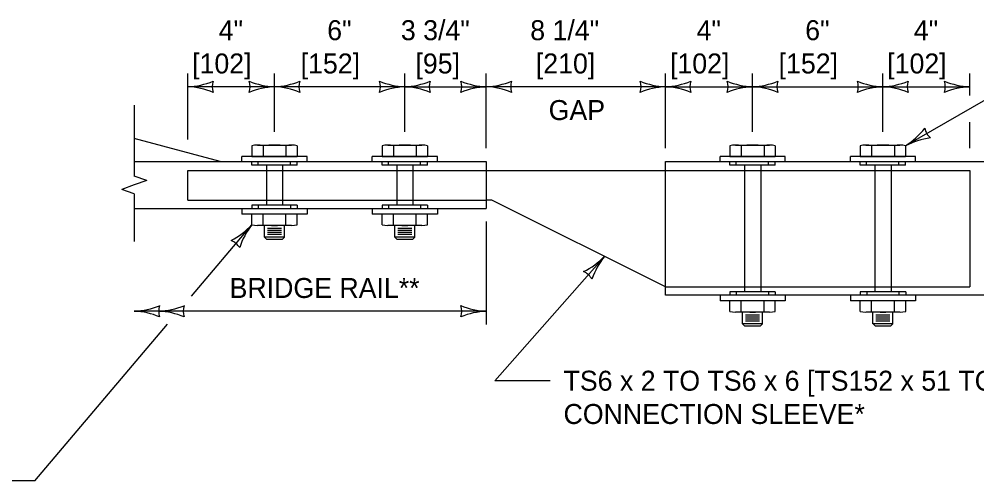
# Model space of a CAD drawing. Extents: x 49991.4 to 50021, y 49987.6 to 50011.4.
# Drawn here: x 50011.465 to 50014.342, y 49993.536 to 49994.923 of the extents above; entities that cross this region are included whole.
import ezdxf

# ---------------------------------------------------------------- set-up
doc = ezdxf.new("R2010")
doc.units = 0
for name, color, linetype in [('Level 1', 7, 'Continuous'), ('Level 2', 7, 'Continuous'), ('Level 3', 7, 'Continuous'), ('Level 4', 7, 'Continuous'), ('Level 6', 7, 'Continuous')]:
    doc.layers.add(name, color=color, linetype=linetype)

msp = doc.modelspace()

# ---------------------------------------------------------------- linework, layer by layer
at = {"layer": 'Level 1'}
for p, q in [((50012.0685, 49994.495), (50011.8107, 49994.5642)), ((50012.1636, 49994.5423), (50012.1636, 49994.5105)), ((50012.1807, 49994.5444), (50012.2828, 49994.5444)), ((50012.1974, 49994.5423), (50012.1974, 49994.5106)), ((50012.2662, 49994.5423), (50012.2662, 49994.5106)), ((50012.3, 49994.5423), (50012.3, 49994.5105)), ((50012.5551, 49994.5424), (50012.5551, 49994.5106)), ((50012.5722, 49994.5445), (50012.6743, 49994.5445)), ((50012.5889, 49994.5425), (50012.5889, 49994.5107)), ((50012.6577, 49994.5425), (50012.6577, 49994.5107)), ((50012.6915, 49994.5424), (50012.6915, 49994.5106)), ((50013.5997, 49994.5424), (50013.5997, 49994.5106)), ((50013.6168, 49994.5445), (50013.7189, 49994.5445)), ((50013.6335, 49994.5424), (50013.6335, 49994.5107)), ((50013.7023, 49994.5424), (50013.7023, 49994.5107)), ((50013.7361, 49994.5424), (50013.7361, 49994.5106)), ((50013.9913, 49994.5424), (50013.9913, 49994.5106)), ((50014.0084, 49994.5445), (50014.1105, 49994.5445)), ((50014.0251, 49994.5424), (50014.0251, 49994.5107)), ((50014.0939, 49994.5424), (50014.0939, 49994.5107)), ((50014.1277, 49994.5424), (50014.1277, 49994.5106)), ((50012.3295, 49994.5105), (50012.1341, 49994.5105)), ((50012.1341, 49994.495), (50012.1341, 49994.5105)), ((50012.1636, 49994.5105), (50012.3, 49994.5105)), ((50012.3295, 49994.495), (50012.3295, 49994.5105)), ((50012.721, 49994.5106), (50012.5256, 49994.5106)), ((50012.5256, 49994.4951), (50012.5256, 49994.5106)), ((50012.5551, 49994.5106), (50012.6915, 49994.5106)), ((50012.721, 49994.4951), (50012.721, 49994.5106)), ((50013.7656, 49994.5106), (50013.5702, 49994.5106)), ((50013.5702, 49994.4951), (50013.5702, 49994.5106)), ((50013.5997, 49994.5106), (50013.7361, 49994.5106)), ((50013.7656, 49994.4951), (50013.7656, 49994.5106)), ((50014.1572, 49994.5106), (50013.9618, 49994.5106)), ((50013.9618, 49994.4951), (50013.9618, 49994.5106)), ((50013.9913, 49994.5106), (50014.1277, 49994.5106)), ((50014.1572, 49994.4951), (50014.1572, 49994.5106)), ((50011.8107, 49994.495), (50012.8678, 49994.495)), ((50012.8683, 49994.3544), (50012.8683, 49994.4951)), ((50013.4063, 49994.495), (50014.4453, 49994.495)), ((50013.4068, 49994.094), (50013.4068, 49994.4951)), ((50012.8683, 49994.4681), (50013.4068, 49994.4681)), ((50012.868, 49994.3795), (50012.8847, 49994.3795)), ((50013.4068, 49994.1186), (50012.8845, 49994.379)), ((50011.8107, 49994.3544), (50012.8678, 49994.3544)), ((50012.1341, 49994.3544), (50012.1341, 49994.337)), ((50012.3295, 49994.337), (50012.1341, 49994.337)), ((50012.3, 49994.337), (50012.1636, 49994.337)), ((50012.1636, 49994.3052), (50012.1636, 49994.337)), ((50012.1974, 49994.3051), (50012.1974, 49994.3369)), ((50012.2662, 49994.3051), (50012.2662, 49994.3369)), ((50012.3, 49994.3052), (50012.3, 49994.337)), ((50012.3295, 49994.3544), (50012.3295, 49994.337)), ((50012.5256, 49994.3544), (50012.5256, 49994.337)), ((50012.721, 49994.337), (50012.5256, 49994.337)), ((50012.6915, 49994.337), (50012.5551, 49994.337)), ((50012.5551, 49994.3052), (50012.5551, 49994.337)), ((50012.5889, 49994.3051), (50012.5889, 49994.3369)), ((50012.6577, 49994.3051), (50012.6577, 49994.3369)), ((50012.6915, 49994.3052), (50012.6915, 49994.337)), ((50012.721, 49994.3544), (50012.721, 49994.337)), ((50012.2829, 49994.3031), (50012.1808, 49994.3031)), ((50012.2018, 49994.2675), (50012.2018, 49994.303)), ((50012.2618, 49994.2675), (50012.2618, 49994.303)), ((50012.6744, 49994.3031), (50012.5723, 49994.3031)), ((50012.5933, 49994.2675), (50012.5933, 49994.303)), ((50012.6533, 49994.2675), (50012.6533, 49994.303)), ((50012.2106, 49994.2947), (50012.2527, 49994.2947)), ((50012.2106, 49994.2887), (50012.2527, 49994.2887)), ((50012.2106, 49994.2827), (50012.2527, 49994.2827)), ((50012.2106, 49994.2767), (50012.2527, 49994.2767)), ((50012.6021, 49994.2947), (50012.6442, 49994.2947)), ((50012.6021, 49994.2887), (50012.6442, 49994.2887)), ((50012.6021, 49994.2827), (50012.6442, 49994.2827)), ((50012.6021, 49994.2767), (50012.6442, 49994.2767)), ((50012.2618, 49994.2675), (50012.2018, 49994.2675)), ((50012.2019, 49994.2676), (50012.2079, 49994.2616)), ((50012.2079, 49994.2616), (50012.2558, 49994.2616)), ((50012.2617, 49994.2676), (50012.2558, 49994.2616)), ((50012.6533, 49994.2675), (50012.5933, 49994.2675)), ((50012.5934, 49994.2676), (50012.5994, 49994.2616)), ((50012.5994, 49994.2616), (50012.6473, 49994.2616)), ((50012.6532, 49994.2676), (50012.6473, 49994.2616)), ((50013.4063, 49994.0942), (50014.4453, 49994.0942)), ((50013.5702, 49994.094), (50013.5702, 49994.0766)), ((50013.7656, 49994.0766), (50013.5702, 49994.0766)), ((50013.7361, 49994.0766), (50013.5997, 49994.0766)), ((50013.5997, 49994.0448), (50013.5997, 49994.0766)), ((50013.6335, 49994.0447), (50013.6335, 49994.0765)), ((50013.7023, 49994.0447), (50013.7023, 49994.0765)), ((50013.7361, 49994.0448), (50013.7361, 49994.0766)), ((50013.7656, 49994.094), (50013.7656, 49994.0766)), ((50013.962, 49994.094), (50013.962, 49994.0766)), ((50014.1574, 49994.0766), (50013.962, 49994.0766)), ((50014.1279, 49994.0766), (50013.9915, 49994.0766)), ((50013.9915, 49994.0448), (50013.9915, 49994.0766)), ((50014.0253, 49994.0447), (50014.0253, 49994.0765)), ((50014.0941, 49994.0447), (50014.0941, 49994.0765)), ((50014.1279, 49994.0448), (50014.1279, 49994.0766)), ((50014.1574, 49994.094), (50014.1574, 49994.0766)), ((50013.719, 49994.0427), (50013.6169, 49994.0427)), ((50013.6379, 49994.0071), (50013.6379, 49994.0426)), ((50013.6467, 49994.0343), (50013.6888, 49994.0343)), ((50013.6467, 49994.0283), (50013.6888, 49994.0283)), ((50013.6467, 49994.0223), (50013.6888, 49994.0223)), ((50013.6467, 49994.0163), (50013.6888, 49994.0163)), ((50013.6979, 49994.0071), (50013.6979, 49994.0426)), ((50014.1108, 49994.0427), (50014.0087, 49994.0427)), ((50014.0297, 49994.0071), (50014.0297, 49994.0426)), ((50014.0385, 49994.0343), (50014.0806, 49994.0343)), ((50014.0385, 49994.0283), (50014.0806, 49994.0283)), ((50014.0385, 49994.0223), (50014.0806, 49994.0223)), ((50014.0385, 49994.0163), (50014.0806, 49994.0163)), ((50014.0897, 49994.0071), (50014.0897, 49994.0426)), ((50013.6979, 49994.0071), (50013.6379, 49994.0071)), ((50013.638, 49994.0072), (50013.644, 49994.0012)), ((50013.644, 49994.0012), (50013.6919, 49994.0012)), ((50013.6978, 49994.0072), (50013.6919, 49994.0012)), ((50014.0897, 49994.0071), (50014.0297, 49994.0071)), ((50014.0298, 49994.0072), (50014.0358, 49994.0012)), ((50014.0358, 49994.0012), (50014.0837, 49994.0012)), ((50014.0896, 49994.0072), (50014.0837, 49994.0012))]:
    msp.add_line(p, q, dxfattribs=at)
for centre, major_axis, start_param, end_param in [((50012.1806, 49994.5283), (0.0341, 0), 1.056847, 2.094396), ((50012.2318, 49994.4801), (0.1365, 0), 1.315951, 1.825641), ((50012.283, 49994.5283), (0.0341, 0), 1.047198, 2.084746), ((50012.5721, 49994.5284), (0.0341, 0), 1.056847, 2.094396), ((50012.6233, 49994.4802), (0.1365, 0), 1.315951, 1.825641), ((50012.6745, 49994.5284), (0.0341, 0), 1.047198, 2.084746), ((50013.6167, 49994.5284), (0.0341, 0), 1.056847, 2.094396), ((50013.6679, 49994.4802), (0.1365, 0), 1.315951, 1.825641), ((50013.7191, 49994.5284), (0.0341, 0), 1.047198, 2.084746), ((50014.0083, 49994.5284), (0.0341, 0), 1.056847, 2.094396), ((50014.0595, 49994.4802), (0.1365, 0), 1.315951, 1.825641), ((50014.1107, 49994.5284), (0.0341, 0), 1.047198, 2.084746), ((50012.1806, 49994.3192), (-0.0341, 0), 1.047198, 2.084746), ((50012.2318, 49994.3674), (-0.1365, 0), 1.315951, 1.825641), ((50012.283, 49994.3192), (-0.0341, 0), 1.056847, 2.094396), ((50012.5721, 49994.3192), (-0.0341, 0), 1.047198, 2.084746), ((50012.6233, 49994.3674), (-0.1365, 0), 1.315951, 1.825641), ((50012.6745, 49994.3192), (-0.0341, 0), 1.056847, 2.094396), ((50013.6167, 49994.0588), (-0.0341, 0), 1.047198, 2.084746), ((50013.6679, 49994.107), (-0.1365, 0), 1.315951, 1.825641), ((50013.7191, 49994.0588), (-0.0341, 0), 1.056847, 2.094396), ((50014.0085, 49994.0588), (-0.0341, 0), 1.047198, 2.084746), ((50014.0597, 49994.107), (-0.1365, 0), 1.315951, 1.825641), ((50014.1109, 49994.0588), (-0.0341, 0), 1.056847, 2.094396)]:
    msp.add_ellipse(centre, major_axis=major_axis, ratio=0.471622, start_param=start_param, end_param=end_param, dxfattribs=at)
at = {"layer": 'Level 3'}
for p, q in [((50014.7294, 49994.8897), (50014.1277, 49994.5424)), ((50011.9713, 49994.5611), (50011.9713, 49994.7597)), ((50012.2317, 49994.5844), (50012.2317, 49994.7597)), ((50012.6232, 49994.5845), (50012.6232, 49994.7597)), ((50012.8678, 49994.535), (50012.8678, 49994.7597)), ((50013.4063, 49994.535), (50013.4063, 49994.7597)), ((50013.6678, 49994.5845), (50013.6678, 49994.7597)), ((50014.059, 49994.5845), (50014.059, 49994.7597)), ((50014.3204, 49994.6936), (50014.3204, 49994.7597)), ((50012.2317, 49994.7197), (50011.9713, 49994.7197)), ((50012.6232, 49994.7197), (50012.2317, 49994.7197)), ((50012.6232, 49994.7197), (50012.8678, 49994.7197)), ((50013.4063, 49994.7197), (50012.8678, 49994.7197)), ((50013.4063, 49994.7197), (50013.6678, 49994.7197)), ((50013.6678, 49994.7197), (50014.059, 49994.7197)), ((50014.059, 49994.7197), (50014.3204, 49994.7197)), ((50014.3204, 49994.535), (50014.3204, 49994.6136)), ((50011.9822, 49994.0909), (50012.1636, 49994.3052)), ((50012.8678, 49994.3144), (50012.8678, 49994.0052)), ((50012.8937, 49993.8365), (50013.2232, 49994.2102)), ((50012.8678, 49994.0452), (50011.8107, 49994.0452)), ((50011.5123, 49993.5356), (50011.9105, 49994.0062)), ((50013.0601, 49993.8365), (50012.8937, 49993.8365)), ((50011.5123, 49993.5356), (50010.9895, 49993.5356))]:
    msp.add_line(p, q, dxfattribs=at)
for centre, radius, start, end in [((50011.9598, 49994.9524), 0.233, 272.8273, 292.0772), ((50012.0995, 49994.7197), 0.0548, 162.1388, 197.8612), ((50012.2409, 49994.9418), 0.2223, 247.456, 267.6395), ((50012.1035, 49994.7197), 0.0548, 342.1388, 17.8612), ((50012.2203, 49994.9524), 0.233, 272.8273, 292.0772), ((50012.36, 49994.7197), 0.0548, 162.1388, 197.8612), ((50012.6324, 49994.9418), 0.2223, 247.456, 267.6395), ((50012.495, 49994.7197), 0.0548, 342.1388, 17.8612), ((50012.6118, 49994.9524), 0.233, 272.8273, 292.0772), ((50012.7515, 49994.7197), 0.0548, 162.1388, 197.8612), ((50012.877, 49994.9418), 0.2223, 247.456, 267.6395), ((50012.7396, 49994.7197), 0.0548, 342.1388, 17.8612), ((50012.8563, 49994.9524), 0.233, 272.8273, 292.0772), ((50012.9961, 49994.7197), 0.0548, 162.1388, 197.8612), ((50013.4155, 49994.9418), 0.2223, 247.456, 267.6395), ((50013.2781, 49994.7197), 0.0548, 342.1388, 17.8612), ((50013.3948, 49994.9524), 0.233, 272.8273, 292.0772), ((50013.5346, 49994.7197), 0.0548, 162.1388, 197.8612), ((50013.6769, 49994.9418), 0.2223, 247.456, 267.6395), ((50013.5395, 49994.7197), 0.0548, 342.1388, 17.8612), ((50013.6563, 49994.9524), 0.233, 272.8273, 292.0772), ((50013.796, 49994.7197), 0.0548, 162.1388, 197.8612), ((50014.0681, 49994.9418), 0.2223, 247.456, 267.6395), ((50013.9307, 49994.7197), 0.0548, 342.1388, 17.8612), ((50014.0475, 49994.9524), 0.233, 272.8273, 292.0772), ((50014.1872, 49994.7197), 0.0548, 162.1388, 197.8612), ((50014.3295, 49994.9418), 0.2223, 247.456, 267.6395), ((50014.1921, 49994.7197), 0.0548, 342.1388, 17.8612), ((50011.9621, 49994.4976), 0.2223, 67.456, 87.6395), ((50012.2432, 49994.487), 0.233, 92.8273, 112.0772), ((50012.2226, 49994.4976), 0.2223, 67.456, 87.6395), ((50012.6347, 49994.487), 0.233, 92.8273, 112.0772), ((50012.6141, 49994.4976), 0.2223, 67.456, 87.6395), ((50012.8793, 49994.487), 0.233, 92.8273, 112.0772), ((50012.8587, 49994.4976), 0.2223, 67.456, 87.6395), ((50013.4178, 49994.487), 0.233, 92.8273, 112.0772), ((50013.3972, 49994.4976), 0.2223, 67.456, 87.6395), ((50013.6792, 49994.487), 0.233, 92.8273, 112.0772), ((50013.6586, 49994.4976), 0.2223, 67.456, 87.6395), ((50014.0704, 49994.487), 0.233, 92.8273, 112.0772), ((50014.0498, 49994.4976), 0.2223, 67.456, 87.6395), ((50014.3319, 49994.487), 0.233, 92.8273, 112.0772), ((50014.0014, 49994.7382), 0.233, 302.8248, 322.0747), ((50014.2388, 49994.6065), 0.0548, 192.1363, 227.8587), ((50014.2309, 49994.3454), 0.2223, 97.4535, 117.637), ((50011.9999, 49994.4557), 0.2223, 297.2185, 317.402), ((50012.3486, 49994.1637), 0.233, 142.5898, 161.8396), ((50012.0807, 49994.2073), 0.0548, 31.9013, 67.6237), ((50013.0626, 49994.364), 0.2223, 296.0525, 316.236), ((50013.4054, 49994.0649), 0.233, 141.4238, 160.6737), ((50013.1384, 49994.114), 0.0548, 30.7353, 66.4577), ((50011.7992, 49994.2779), 0.233, 272.8273, 292.0772), ((50011.8015, 49993.823), 0.2223, 67.456, 87.6395), ((50011.8726, 49994.2779), 0.233, 272.8273, 292.0772), ((50011.9389, 49994.0452), 0.0548, 162.1388, 197.8612), ((50011.875, 49993.823), 0.2223, 67.456, 87.6395), ((50012.0124, 49994.0452), 0.0548, 162.1388, 197.8612), ((50012.877, 49994.2673), 0.2223, 247.456, 267.6395), ((50012.7396, 49994.0452), 0.0548, 342.1388, 17.8612), ((50012.8793, 49993.8125), 0.233, 92.8273, 112.0772)]:
    msp.add_arc(centre, radius, start, end, dxfattribs=at)
at = {"layer": 'Level 4'}
for p, q in [((50012.1635, 49994.484), (50012.1635, 49994.495)), ((50012.3, 49994.484), (50012.1635, 49994.484)), ((50012.1828, 49994.484), (50012.1828, 49994.495)), ((50012.2076, 49994.484), (50012.2076, 49994.3644)), ((50012.2563, 49994.484), (50012.2563, 49994.3644)), ((50012.2794, 49994.484), (50012.2794, 49994.495)), ((50012.3, 49994.484), (50012.3, 49994.495)), ((50012.555, 49994.4841), (50012.555, 49994.4951)), ((50012.6915, 49994.4841), (50012.555, 49994.4841)), ((50012.5743, 49994.4841), (50012.5743, 49994.4951)), ((50012.5991, 49994.4841), (50012.5991, 49994.3644)), ((50012.6478, 49994.4841), (50012.6478, 49994.3644)), ((50012.6709, 49994.4841), (50012.6709, 49994.4951)), ((50012.6915, 49994.4841), (50012.6915, 49994.4951)), ((50013.5996, 49994.4841), (50013.5996, 49994.4951)), ((50013.7361, 49994.4841), (50013.5996, 49994.4841)), ((50013.6189, 49994.4841), (50013.6189, 49994.4951)), ((50013.6437, 49994.4841), (50013.6437, 49994.104)), ((50013.6924, 49994.4841), (50013.6924, 49994.104)), ((50013.7155, 49994.4841), (50013.7155, 49994.4951)), ((50013.7361, 49994.4841), (50013.7361, 49994.4951)), ((50013.9912, 49994.4841), (50013.9912, 49994.4951)), ((50014.1277, 49994.4841), (50013.9912, 49994.4841)), ((50014.0105, 49994.4841), (50014.0105, 49994.4951)), ((50014.0355, 49994.4841), (50014.0355, 49994.104)), ((50014.0842, 49994.4841), (50014.0842, 49994.104)), ((50014.1071, 49994.4841), (50014.1071, 49994.4951)), ((50014.1277, 49994.4841), (50014.1277, 49994.4951)), ((50011.9713, 49994.379), (50011.9713, 49994.4681)), ((50011.9713, 49994.4681), (50012.8683, 49994.4681)), ((50013.4064, 49994.4682), (50014.3204, 49994.4682)), ((50014.3204, 49994.4682), (50014.3204, 49994.1187)), ((50011.9713, 49994.379), (50012.8683, 49994.379)), ((50012.3, 49994.3644), (50012.1635, 49994.3644)), ((50012.1635, 49994.3644), (50012.1635, 49994.3544)), ((50012.1828, 49994.3644), (50012.1828, 49994.3544)), ((50012.2794, 49994.3644), (50012.2794, 49994.3544)), ((50012.3, 49994.3644), (50012.3, 49994.3544)), ((50012.6915, 49994.3644), (50012.555, 49994.3644)), ((50012.555, 49994.3644), (50012.555, 49994.3544)), ((50012.5743, 49994.3644), (50012.5743, 49994.3544)), ((50012.6709, 49994.3644), (50012.6709, 49994.3544)), ((50012.6915, 49994.3644), (50012.6915, 49994.3544)), ((50013.4064, 49994.1187), (50014.3204, 49994.1187)), ((50013.7361, 49994.104), (50013.5996, 49994.104)), ((50013.5996, 49994.104), (50013.5996, 49994.094)), ((50013.6189, 49994.104), (50013.6189, 49994.094)), ((50013.7155, 49994.104), (50013.7155, 49994.094)), ((50013.7361, 49994.104), (50013.7361, 49994.094)), ((50014.1279, 49994.104), (50013.9914, 49994.104)), ((50013.9914, 49994.104), (50013.9914, 49994.094)), ((50014.0107, 49994.104), (50014.0107, 49994.094)), ((50014.1073, 49994.104), (50014.1073, 49994.094)), ((50014.1279, 49994.104), (50014.1279, 49994.094))]:
    msp.add_line(p, q, dxfattribs=at)
at = {"layer": 'Level 6'}
for p, q in [((50011.8107, 49994.6641), (50011.8107, 49994.4515)), ((50011.8486, 49994.4382), (50011.8107, 49994.4515)), ((50011.8107, 49994.4247), (50011.7728, 49994.4112)), ((50011.8486, 49994.4382), (50011.8107, 49994.4247)), ((50011.8107, 49994.3979), (50011.7728, 49994.4112)), ((50011.8107, 49994.3979), (50011.8107, 49994.2544))]:
    msp.add_line(p, q, dxfattribs=at)

# ---------------------------------------------------------------- texts
at = {"layer": 'Level 2'}
for s, p in [('4"', (50012.0643, 49994.8597)), ('6"', (50012.3902, 49994.8597)), ('3 3/4"', (50012.6115, 49994.8597)), ('8 1/4"', (50013.0001, 49994.8597)), ('4"', (50013.4998, 49994.8597)), ('6"', (50013.8261, 49994.8597)), ('4"', (50014.1524, 49994.8597)), ('[102]', (50011.9844, 49994.7597)), ('[152]', (50012.3104, 49994.7597)), ('[95]', (50012.6553, 49994.7597)), ('[210]', (50013.017, 49994.7597)), ('[102]', (50013.4199, 49994.7597)), ('[152]', (50013.7462, 49994.7597)), ('[102]', (50014.0725, 49994.7597)), ('GAP', (50013.0554, 49994.6197)), ('BRIDGE RAIL**', (50012.0969, 49994.0851)), ('TS6 x 2 TO TS6 x 6 [TS152 x 51 TO TS152 x 152] ', (50013.1001, 49993.8065)), ('CONNECTION SLEEVE*', (50013.1001, 49993.7065))]:
    msp.add_text(s, height=0.06, dxfattribs=at).set_placement(p)

doc.saveas('drawing.dxf')
